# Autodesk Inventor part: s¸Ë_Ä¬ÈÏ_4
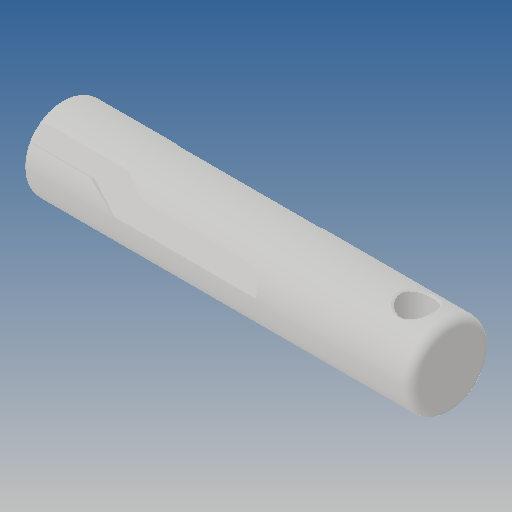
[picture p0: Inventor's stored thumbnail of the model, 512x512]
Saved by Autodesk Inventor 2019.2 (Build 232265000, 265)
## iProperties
Created: 2013-03
Part Number: s¸Ë_Ä¬ÈÏ_4
Material: Ogólny
Document SubType Name: Modeling
Designer: CADENGINEERING4
Density: 1 g/cm^3
Appearance: Domyślna
Author: CADENGINEERING4
Revision Number: ÈÎºÎ
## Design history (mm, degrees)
feature "NONE"
node "Bryła1"
